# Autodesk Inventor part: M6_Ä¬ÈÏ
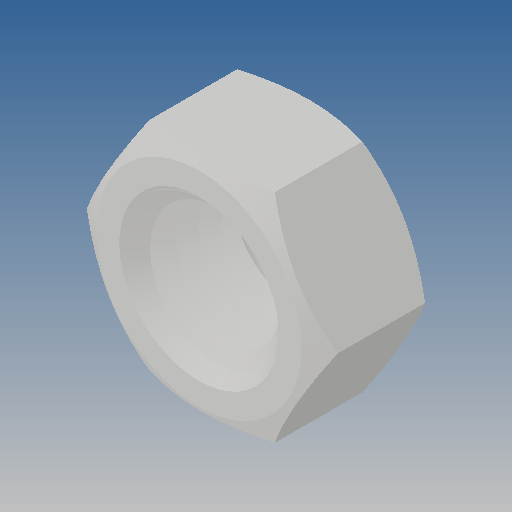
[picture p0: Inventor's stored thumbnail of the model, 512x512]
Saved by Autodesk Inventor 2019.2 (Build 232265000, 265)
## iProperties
Created: 2010-06
Part Number: M6_Ä¬ÈÏ
Material: Ogólny
Document SubType Name: Modeling
Designer: CADENGINEERING4
Density: 1 g/cm^3
Appearance: Domyślna
Author: CADENGINEERING4
Revision Number: ÈÎºÎ
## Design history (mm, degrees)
feature "NONE"
node "Bryła1"
